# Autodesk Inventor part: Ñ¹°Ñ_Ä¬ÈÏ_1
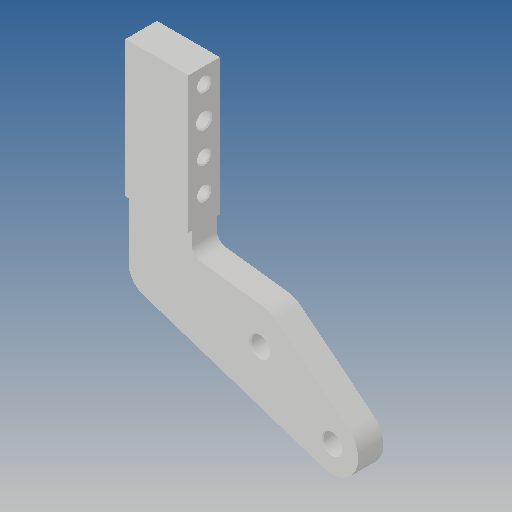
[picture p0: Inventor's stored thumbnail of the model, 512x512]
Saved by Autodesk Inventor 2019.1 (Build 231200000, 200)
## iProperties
Created: 2012-10
Part Number: Ñ¹°Ñ_Ä¬ÈÏ_1
Material: Ogólny
Document SubType Name: Modeling
Designer: CADENGINEERING4
Density: 1 g/cm^3
Appearance: Domyślna
Author: CADENGINEERING4
Revision Number: ÈÎºÎ
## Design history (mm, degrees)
feature "NONE"
node "Bryła1"
